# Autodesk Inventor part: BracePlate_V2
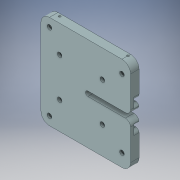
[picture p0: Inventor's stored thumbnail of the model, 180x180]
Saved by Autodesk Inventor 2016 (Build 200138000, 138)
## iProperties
Created: 2016-01
Part Number: BracePlate_V2
Material: Generic
Document SubType Name: Modeling
Designer: John
Density: 1 g/cm^3
Appearance: Default
Author: John
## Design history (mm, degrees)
feature "Base1"
sketch "Sketch3"
  geometry: L1 (-4, 37.62)-(25, 37.62) reference; L2 (25, 32.02)-(-4, 32.02) reference; L3 (-6, 24.02)-(10.75, 24.02) reference; L4 (10.75, 19.52)-(-6, 19.52) reference; L5 (-10, 10)-(-10, 15.52) reference; L6 (50, 0)-(0, 0) reference; L7 (60, 59.64)-(60, 10) reference; L8 (0, 69.64)-(50, 69.64) reference; L9 (-10, 56.12)-(-10, 59.64) reference; L10 (-6, 52.12)-(10.75, 52.12) reference; L11 (10.75, 47.62)-(-6, 47.62) reference; L12 (3.95, 9.691)-(3.95, 14.309) reference; L13 (-0.05, 7.381)-(3.95, 9.691) reference; L14 (-4.05, 9.691)-(-0.05, 7.381) reference; L15 (-4.05, 14.309)-(-4.05, 9.691) reference; L16 (-0.05, 16.619)-(-4.05, 14.309) reference; L17 (3.95, 14.309)-(-0.05, 16.619) reference; L18 (54.05, 9.691)-(54.05, 14.309) reference; L19 (50.05, 7.381)-(54.05, 9.691) reference; L20 (46.05, 9.691)-(50.05, 7.381) reference; L21 (46.05, 14.309)-(46.05, 9.691) reference; L22 (50.05, 16.619)-(46.05, 14.309) reference; L23 (54.05, 14.309)-(50.05, 16.619) reference; L24 (54.05, 55.331)-(54.05, 59.949) reference; L25 (50.05, 53.021)-(54.05, 55.331) reference; L26 (46.05, 55.331)-(50.05, 53.021) reference; L27 (46.05, 59.949)-(46.05, 55.331) reference; L28 (50.05, 62.259)-(46.05, 59.949) reference; L29 (54.05, 59.949)-(50.05, 62.259) reference; L30 (3.95, 59.949)-(-0.05, 62.259) reference; L31 (3.95, 55.331)-(3.95, 59.949) reference; L32 (-0.05, 53.021)-(3.95, 55.331) reference; L33 (-4.05, 55.331)-(-0.05, 53.021) reference; L34 (-4.05, 59.949)-(-4.05, 55.331) reference; L35 (-0.05, 62.259)-(-4.05, 59.949) reference; L36 (27.8, 57.88)-(27.8, 12.76); L37 (-10, 12.76)-(-10, 57.88); L38 (27.8, 12.76)-(3.95, 12.76); L39 (-4.05, 12.76)-(-10, 12.76); L40 (-10, 57.88)-(-4.05, 57.88); L41 (3.95, 57.88)-(27.8, 57.88); A1 r 4 centre (-6, 43.62) between (-6, 47.62) and (-10, 43.62) reference; A2 r 6 centre (-4, 43.62) between (-10, 43.62) and (-4, 37.62) reference; A3 r 2.8 centre (25, 34.82) between (25, 32.02) and (25, 37.62) reference; A4 r 6 centre (-4, 26.02) between (-4, 32.02) and (-9.898, 27.122) reference; A5 r 4 centre (-6, 28.02) between (-9.898, 27.122) and (-6, 24.02) reference; A6 r 2.25 centre (10.75, 21.77) between (10.75, 19.52) and (10.75, 24.02) reference; A7 r 4 centre (-6, 15.52) between (-6, 19.52) and (-10, 15.52) reference; A8 r 10 centre (0, 10) between (-10, 10) and (0, 0) reference; A9 r 10 centre (50, 10) between (50, 0) and (60, 10) reference; A10 r 10 centre (50, 59.64) between (60, 59.64) and (50, 69.64) reference; A11 r 10 centre (0, 59.64) between (0, 69.64) and (-10, 59.64) reference; A12 r 4 centre (-6, 56.12) between (-10, 56.12) and (-6, 52.12) reference; A13 r 2.25 centre (10.75, 49.87) between (10.75, 47.62) and (10.75, 52.12) reference; 1 further point
  constraints: 12 end point, 5 parallel, 4 point on line, 2 horizontal, 2 midpoint, 2 perpendicular, 1 tangent
  dimensions: "d2" = 13.05 vertical distance of A3.centre A6.centre (derived)
extrude "Extrusion1" join sketch "Sketch3" stored distance "d3" = 10; taper "d4" = 0 deg
sketch "Sketch4" dims "d7" = 5
  geometry: L1 (-10, 45.37)-(10.75, 45.37); L2 (10.75, 45.37)-(10.75, 50.37); L3 (10.75, 50.37)-(-10, 50.37); L4 (-10, 50.37)-(-10, 45.37); L5 (-10, 24.27)-(10.75, 24.27); L6 (10.75, 24.27)-(10.75, 19.27); L7 (10.75, 19.27)-(-10, 19.27); L8 (-10, 19.27)-(-10, 24.27); L9 (-10, 37.62)-(25, 37.62); L10 (25, 37.62)-(25, 32.02); L11 (25, 32.02)-(-10, 32.02); L12 (-10, 32.02)-(-10, 37.62); L13 (-10, 10)-(-10, 59.64) reference; A1 r 2.8 centre (25, 34.82) between (25, 32.02) and (25, 37.62) reference; A2 r 2.25 centre (10.75, 21.77) between (10.75, 19.52) and (10.75, 24.02) reference; A3 r 2.8 centre (25, 34.82) between (25, 37.62) and (25, 37.62); 7 further points
  constraints: 24 end point, 6 coincident, 6 parallel, 5 vertical alignment, 3 horizontal, 3 midpoint, 3 perpendicular, 3 point on line, 2 point on circle, 1 centre point, 8 other
  dimensions: "d5" = 13.05 vertical distance of A1.centre A2.centre (derived); "d6" = 13.05 vertical distance of A1.centre point (10.75, 47.87) (= d5)
extrude "Extrusion2" cut sketch "Sketch4" stored distance "d8" = 10; taper "d9" = 0 deg
extrude "Extrusion3" cut sketch "Sketch4" distance "d10" = 6; taper "d11" = 0 deg
sketch "Sketch5"
  geometry: L1 (3.95, 55.331)-(3.95, 59.949) reference; L2 (-0.05, 53.021)-(3.95, 55.331) reference; L3 (-4.05, 55.331)-(-0.05, 53.021) reference; L4 (-4.05, 59.949)-(-4.05, 55.331) reference; L5 (-0.05, 62.259)-(-4.05, 59.949) reference; L6 (3.95, 59.949)-(-0.05, 62.259) reference; L7 (54.05, 9.691)-(54.05, 14.309) reference; L8 (50.05, 7.381)-(54.05, 9.691) reference; L9 (46.05, 9.691)-(50.05, 7.381) reference; L10 (46.05, 14.309)-(46.05, 9.691) reference; L11 (50.05, 16.619)-(46.05, 14.309) reference; L12 (54.05, 14.309)-(50.05, 16.619) reference; L13 (54.05, 55.331)-(54.05, 59.949) reference; L14 (50.05, 53.021)-(54.05, 55.331) reference; L15 (46.05, 55.331)-(50.05, 53.021) reference; L16 (46.05, 59.949)-(46.05, 55.331) reference; L17 (50.05, 62.259)-(46.05, 59.949) reference; L18 (54.05, 59.949)-(50.05, 62.259) reference; L19 (-4.05, 14.309)-(-4.05, 9.691) reference; L20 (-0.05, 16.619)-(-4.05, 14.309) reference; L21 (3.95, 14.309)-(-0.05, 16.619) reference; L22 (3.95, 9.691)-(3.95, 14.309) reference; L23 (-0.05, 7.381)-(3.95, 9.691) reference; L24 (-4.05, 9.691)-(-0.05, 7.381) reference; L25 (-10, 50.37)-(10.75, 50.37) reference; L26 (10.75, 45.37)-(-10, 45.37) reference; L27 (-10, 37.62)-(-10, 45.37) reference; L28 (-10, 37.62)-(25, 37.62) reference; L29 (25, 32.02)-(-10, 32.02) reference; L30 (-10, 24.27)-(-10, 32.02) reference; L31 (-10, 24.27)-(10.75, 24.27) reference; L32 (10.75, 19.27)-(-10, 19.27) reference; L33 (-10, 10)-(-10, 19.27) reference; L34 (50, 0)-(0, 0) reference; L35 (60, 59.64)-(60, 10) reference; L36 (0, 69.64)-(50, 69.64) reference; L37 (-10, 50.37)-(-10, 59.64) reference; L38 (-25, 84.82)-(75, 84.82); L39 (75, 84.82)-(75, -15.18); L40 (75, -15.18)-(-25, -15.18); L41 (-25, -15.18)-(-25, 84.82); L42 (-10, 50.37)-(-10, 45.37); L43 (-10, 37.62)-(-10, 32.02); L44 (-10, 24.27)-(-10, 19.27); A1 r 2.5 centre (10.75, 47.87) between (10.75, 45.37) and (10.75, 50.37) reference; A2 r 2.8 centre (25, 34.82) between (25, 32.02) and (25, 37.62) reference; A3 r 2.5 centre (10.75, 21.77) between (10.75, 19.27) and (10.75, 24.27) reference; A4 r 10 centre (0, 10) between (-10, 10) and (0, 0) reference; A5 r 10 centre (50, 10) between (50, 0) and (60, 10) reference; A6 r 10 centre (50, 59.64) between (60, 59.64) and (50, 69.64) reference; A7 r 10 centre (0, 59.64) between (0, 69.64) and (-10, 59.64) reference; 5 further points
  constraints: 14 end point, 4 midpoint, 2 collinear, 2 parallel, 1 horizontal, 1 horizontal alignment, 1 perpendicular, 1 vertical, 1 vertical alignment
  dimensions: "d12" = 100 distance of L38.end L39.end; "d13" = 100 distance of L38.start L38.end (= d12)
extrude "Extrusion4" join sketch "Sketch5" stored distance "d14" = 6; taper "d15" = 0 deg
sketch "Sketch6"
  geometry: L1 (15, -47.2)-(50, -47.2) reference; L2 (50, -52.8)-(15, -52.8) reference; L3 (15, -52.8)-(15, -47.2) reference; L4 (15, -39.45)-(15, -34.45) reference; L5 (15, -34.45)-(35.75, -34.45) reference; L6 (35.75, -39.45)-(15, -39.45) reference; L7 (0, 0)-(100, 0) reference; L8 (0, -100)-(0, 0) reference; L9 (100, -100)-(0, -100) reference; L10 (100, 0)-(100, -100) reference; L11 (28.95, -29.489)-(28.95, -24.871) reference; L12 (24.95, -31.799)-(28.95, -29.489) reference; L13 (20.95, -29.489)-(24.95, -31.799) reference; L14 (20.95, -24.871)-(20.95, -29.489) reference; L15 (24.95, -22.561)-(20.95, -24.871) reference; L16 (28.95, -24.871)-(24.95, -22.561) reference; L17 (79.05, -75.129)-(79.05, -70.511) reference; L18 (75.05, -77.439)-(79.05, -75.129) reference; L19 (71.05, -75.129)-(75.05, -77.439) reference; L20 (71.05, -70.511)-(71.05, -75.129) reference; L21 (75.05, -68.201)-(71.05, -70.511) reference; L22 (79.05, -70.511)-(75.05, -68.201) reference; L23 (79.05, -29.489)-(79.05, -24.871) reference; L24 (75.05, -31.799)-(79.05, -29.489) reference; L25 (71.05, -29.489)-(75.05, -31.799) reference; L26 (71.05, -24.871)-(71.05, -29.489) reference; L27 (75.05, -22.561)-(71.05, -24.871) reference; L28 (79.05, -24.871)-(75.05, -22.561) reference; L29 (20.95, -70.511)-(20.95, -75.129) reference; L30 (24.95, -68.201)-(20.95, -70.511) reference; L31 (28.95, -70.511)-(24.95, -68.201) reference; L32 (28.95, -75.129)-(28.95, -70.511) reference; L33 (24.95, -77.439)-(28.95, -75.129) reference; L34 (20.95, -75.129)-(24.95, -77.439) reference; L35 (15, -65.55)-(15, -60.55) reference; L36 (15, -60.55)-(35.75, -60.55) reference; L37 (35.75, -65.55)-(15, -65.55) reference; L38 (15, -39.45)-(0, -39.45); L39 (0, -39.45)-(0, -34.45); L40 (0, -34.45)-(15, -34.45); L41 (15, -34.45)-(15, -39.45); L42 (15, -60.55)-(0, -60.55); L43 (0, -60.55)-(0, -65.55); L44 (0, -65.55)-(15, -65.55); L45 (15, -65.55)-(15, -60.55); L46 (15, -47.2)-(0, -47.2); L47 (0, -47.2)-(0, -52.8); L48 (0, -52.8)-(15, -52.8); L49 (15, -52.8)-(15, -47.2); L50 (0, -100)-(0, 0) reference; A1 r 2.8 centre (50, -50) between (50, -52.8) and (50, -47.2) reference; A2 r 2.5 centre (35.75, -36.95) between (35.75, -39.45) and (35.75, -34.45) reference; A3 r 2.5 centre (35.75, -63.05) between (35.75, -65.55) and (35.75, -60.55) reference; 1 further point
  constraints: 24 end point, 6 parallel, 3 horizontal, 3 perpendicular, 3 point on line
  node "Projected Loop5"
extrude "Extrusion5" cut sketch "Sketch6" stored distance "d16" = 6; taper "d17" = 0 deg
extrude "Extrusion6" cut sketch "Sketch6" stored distance "d18" = 6; taper "d19" = 0 deg
fillet "Fillet1" dims "d20" = 10
sketch "Sketch7"
  geometry: L1 (-40, 50)-(40, 50) reference; L2 (-50, 15.55)-(-50, 40) reference; L3 (-50, 15.55)-(-14.25, 15.55) reference; L4 (-14.25, 10.55)-(-50, 10.55) reference; L5 (-50, 2.8)-(-50, 10.55) reference; L6 (-50, 2.8)-(0, 2.8) reference; L7 (0, -2.8)-(-50, -2.8) reference; L8 (-50, -10.55)-(-50, -2.8) reference; L9 (-50, -10.55)-(-14.25, -10.55) reference; L10 (-14.25, -15.55)-(-50, -15.55) reference; L11 (-50, -40)-(-50, -15.55) reference; L12 (40, -50)-(-40, -50) reference; L13 (50, 40)-(50, -40) reference; L14 (-29.05, -20.511)-(-29.05, -25.129) reference; L15 (-25.05, -18.201)-(-29.05, -20.511) reference; L16 (-21.05, -20.511)-(-25.05, -18.201) reference; L17 (-21.05, -25.129)-(-21.05, -20.511) reference; L18 (-25.05, -27.439)-(-21.05, -25.129) reference; L19 (-29.05, -25.129)-(-25.05, -27.439) reference; L20 (29.05, 20.511)-(29.05, 25.129) reference; L21 (25.05, 18.201)-(29.05, 20.511) reference; L22 (21.05, 20.511)-(25.05, 18.201) reference; L23 (21.05, 25.129)-(21.05, 20.511) reference; L24 (25.05, 27.439)-(21.05, 25.129) reference; L25 (29.05, 25.129)-(25.05, 27.439) reference; L26 (29.05, -25.129)-(29.05, -20.511) reference; L27 (25.05, -27.439)-(29.05, -25.129) reference; L28 (21.05, -25.129)-(25.05, -27.439) reference; L29 (21.05, -20.511)-(21.05, -25.129) reference; L30 (25.05, -18.201)-(21.05, -20.511) reference; L31 (29.05, -20.511)-(25.05, -18.201) reference; L32 (-21.05, 20.511)-(-21.05, 25.129) reference; L33 (-25.05, 18.201)-(-21.05, 20.511) reference; L34 (-29.05, 20.511)-(-25.05, 18.201) reference; L35 (-29.05, 25.129)-(-29.05, 20.511) reference; L36 (-25.05, 27.439)-(-29.05, 25.129) reference; L37 (-21.05, 25.129)-(-25.05, 27.439) reference; L38 (-42.338, 35.95)-(-44.677, 40); L39 (-44.677, 40)-(-42.338, 44.05); L40 (-42.338, 44.05)-(-37.662, 44.05); L41 (-37.662, 44.05)-(-35.323, 40); L42 (-35.323, 40)-(-37.662, 35.95); L43 (-37.662, 35.95)-(-42.338, 35.95); L44 (35.323, 40)-(37.662, 44.05); L45 (37.662, 44.05)-(42.338, 44.05); L46 (42.338, 44.05)-(44.677, 40); L47 (44.677, 40)-(42.338, 35.95); L48 (42.338, 35.95)-(37.662, 35.95); L49 (37.662, 35.95)-(35.323, 40); L50 (42.338, -35.95)-(44.677, -40); L51 (44.677, -40)-(42.338, -44.05); L52 (42.338, -44.05)-(37.662, -44.05); L53 (37.662, -44.05)-(35.323, -40); L54 (35.323, -40)-(37.662, -35.95); L55 (37.662, -35.95)-(42.338, -35.95); L56 (-37.662, -35.95)-(-35.323, -40); L57 (-35.323, -40)-(-37.662, -44.05); L58 (-37.662, -44.05)-(-42.338, -44.05); L59 (-42.338, -44.05)-(-44.677, -40); L60 (-44.677, -40)-(-42.338, -35.95); L61 (-42.338, -35.95)-(-37.662, -35.95); C1 r 2.75 at (-40, 40); C2 r 2.75 at (40, 40); C3 r 2.75 at (40, -40); C4 r 2.75 at (-40, -40); A1 r 10 centre (40, 40) between (50, 40) and (40, 50) reference; A2 r 10 centre (-40, 40) between (-40, 50) and (-50, 40) reference; A3 r 2.5 centre (-14.25, 13.05) between (-14.25, 10.55) and (-14.25, 15.55) reference; A4 r 2.8 centre (0, 0) between (0, -2.8) and (0, 2.8) reference; A5 r 2.5 centre (-14.25, -13.05) between (-14.25, -15.55) and (-14.25, -10.55) reference; A6 r 10 centre (-40, -40) between (-50, -40) and (-40, -50) reference; A7 r 10 centre (40, -40) between (40, -50) and (50, -40) reference; 5 further points
  constraints: 48 end point, 8 coincident, 4 centre point, 4 horizontal, 3 equal length, 3 equal radius, 52 other
  dimensions: "d21" = 8.1 distance between parallel lines of L58 L61; "d24" = 5.5 diameter of C2
  node "Projected Loop6"
extrude "Extrusion7" cut sketch "Sketch7" distance "d22" = 6; taper "d23" = 0 deg
extrude "Extrusion8" cut sketch "Sketch7" stored distance "d25" = 6; taper "d26" = 0 deg
chamfer "Chamfer1" distance "d27" = 1.9; stored, may be unused: second distance "d28" = 2, angle "d29" = 45 deg
sketch "Sketch8"
  geometry: L1 (82.338, 0)-(82.338, 6) reference; L2 (77.662, 0)-(77.662, 6) reference; L3 (2.338, 0)-(2.338, 6) reference; L4 (-2.338, 0)-(-2.338, 6) reference; C1 r 1.25 at (80, 3); C2 r 1.25 at (0, 3); 2 further points
  constraints: 2 centre point, 2 horizontal alignment, 1 equal radius, 1 midpoint
  dimensions: "d30" = 4.67654 distance between parallel lines of L2 L1 (derived); "d31" = 2.33827 distance from line of L2 C1.centre (= 0.5 x d30); "d32" = 2.33827 distance from line of L3 C2.centre (= d31); "d33" = 2.5 diameter of C1
extrude "Extrusion9" cut sketch "Sketch8" stored distance "d34" = 6; taper "d35" = 0 deg
workplane "Work Plane1"
mirror "Mirror1"
fillet "Fillet2" dims "d36" = 4
fillet "Fillet3" dims "d37" = 6
node "Direct Edit1"
node "Direct Edit2"
node "Direct Edit3"
body "Solid1"
node "Projected Loop3"
node "Projected Loop4"
move_body "Move1" dims "d40" = -8
move_body "Move2" dims "d43" = -5
move_body "Move3" dims "d47" = 5
move_body "Move4" dims "d50" = -5
other parameters: "d41" = 0, "d42" = 0, "d44" = 0, "d45" = 0, "d46" = 0, "d48" = 0, "d49" = 0, "d51" = 0
